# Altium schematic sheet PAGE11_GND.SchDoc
size 381 x 304 mm; SheetNumber: 12; SheetTotal: 28
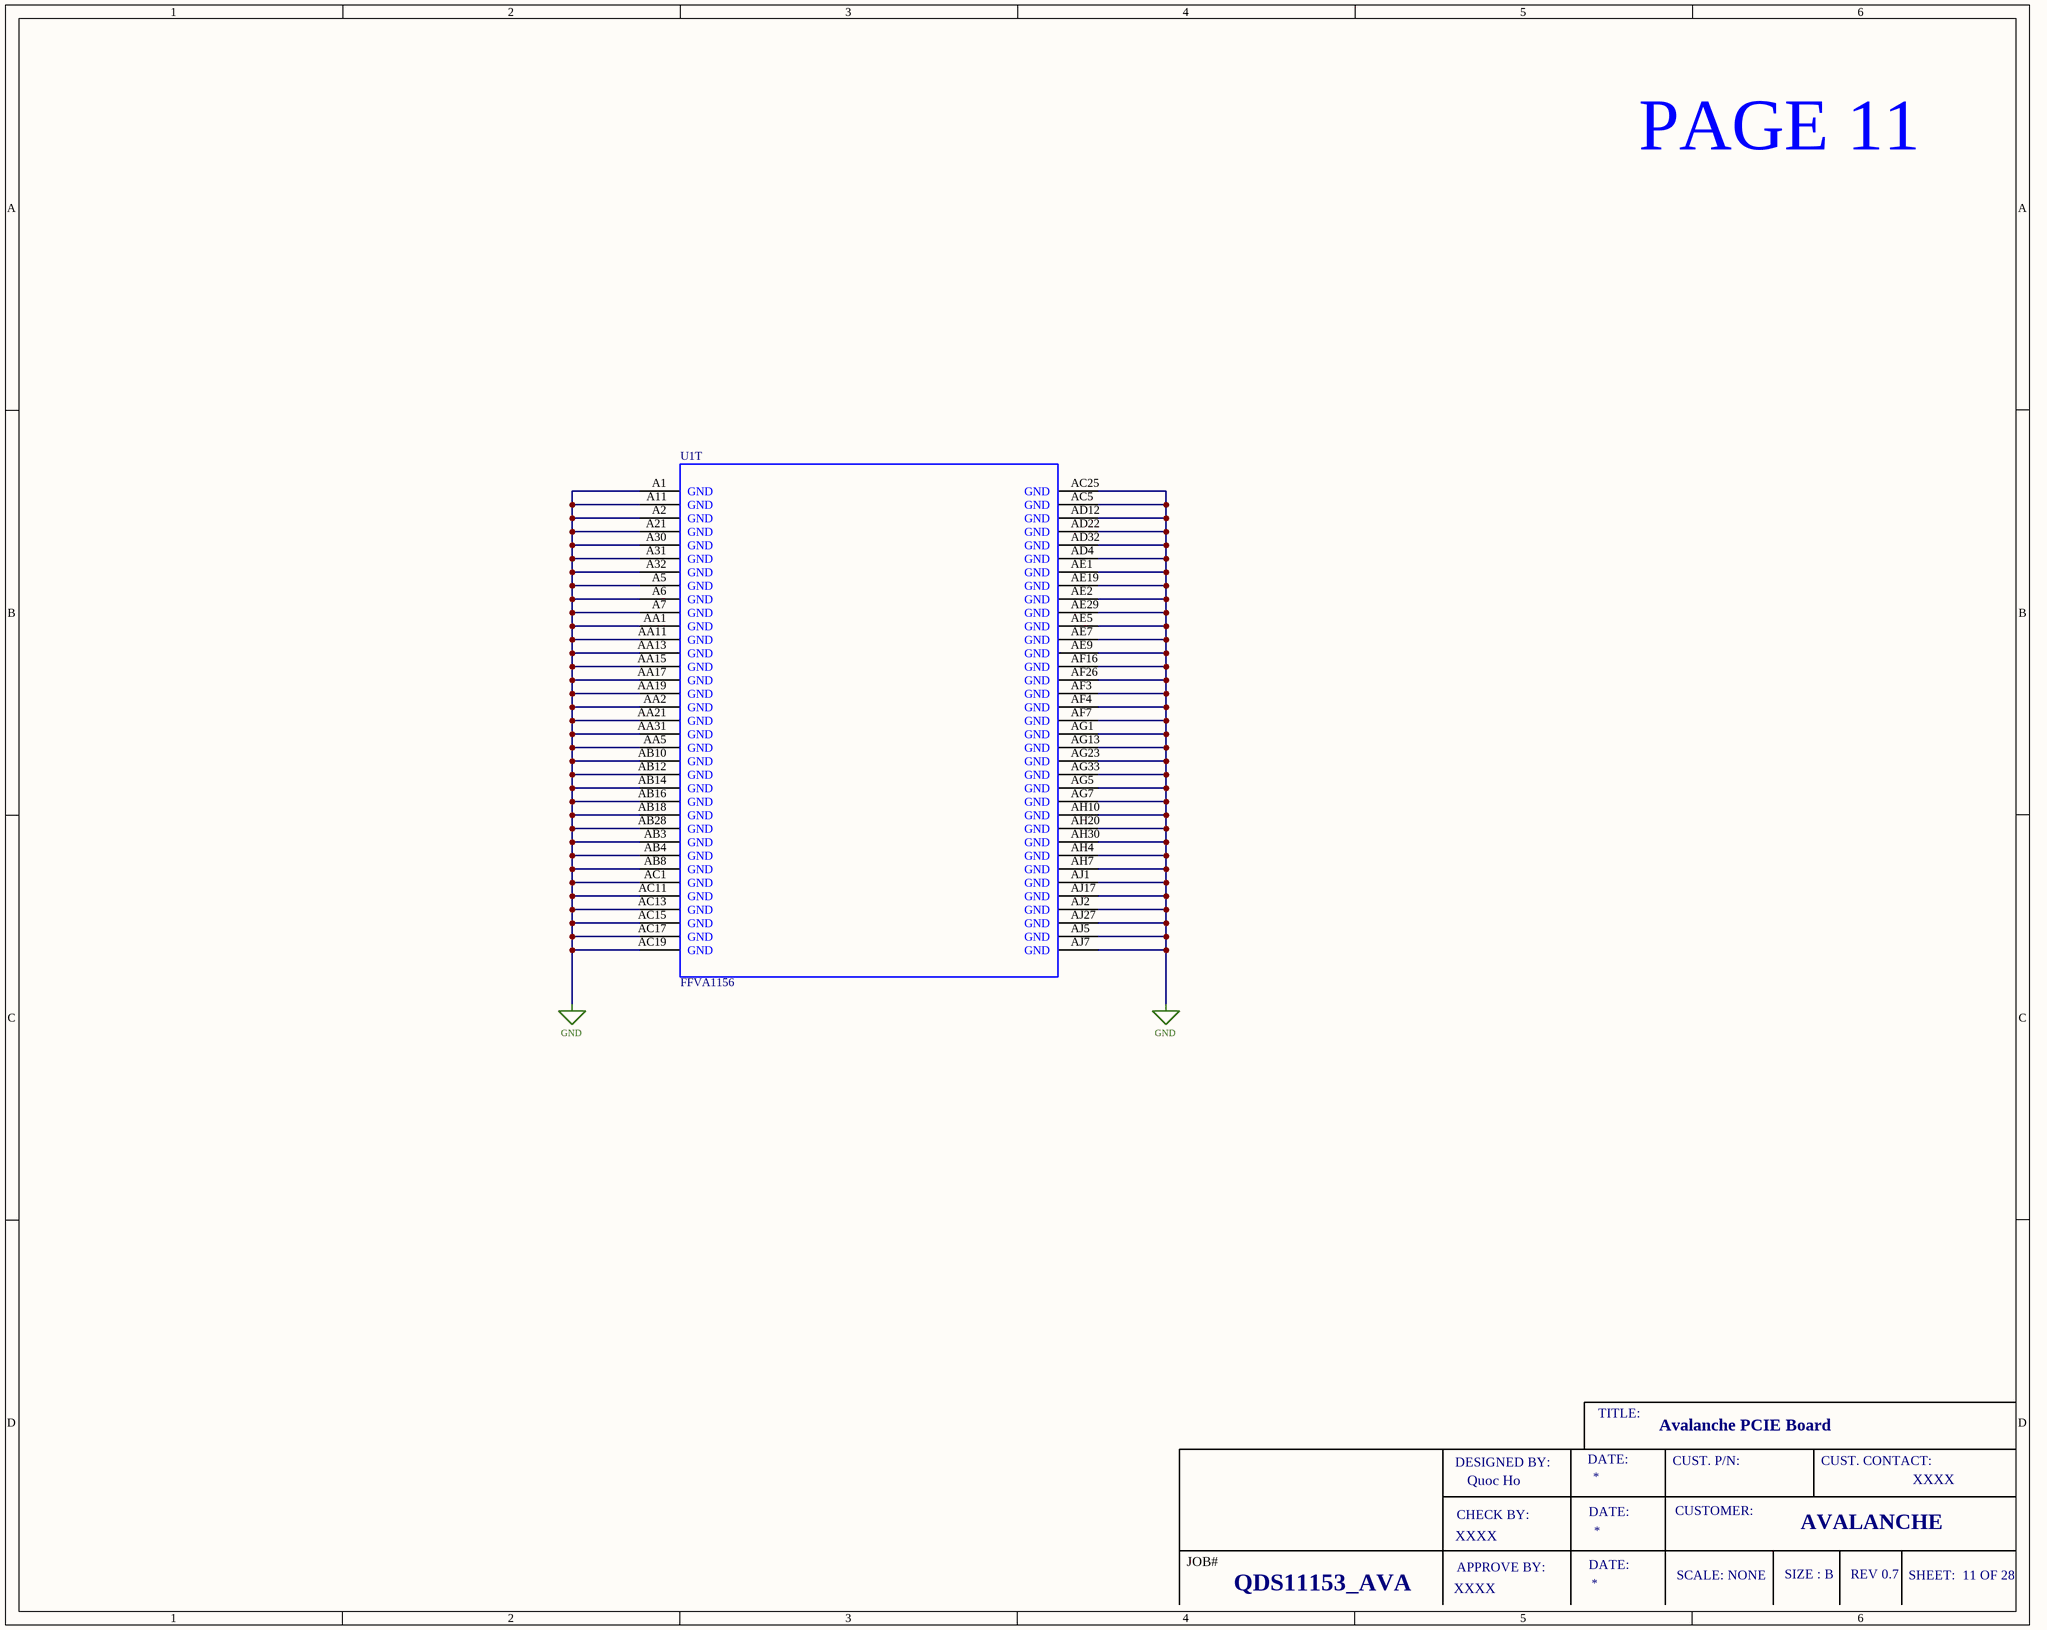
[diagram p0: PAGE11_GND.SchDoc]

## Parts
U1  FFVA1156  [FFVA1156]  (part T of 25)

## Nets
GND: U1.A1(GND) U1.A2(GND) U1.A5(GND) U1.A6(GND) U1.A7(GND) U1.A11(GND) U1.A21(GND) U1.A30(GND) U1.A31(GND) U1.A32(GND) U1.AA1(GND) U1.AA2(GND) U1.AA5(GND) U1.AA11(GND) U1.AA13(GND) U1.AA15(GND) U1.AA17(GND) U1.AA19(GND) U1.AA21(GND) U1.AA31(GND) U1.AB3(GND) U1.AB4(GND) U1.AB8(GND) U1.AB10(GND) U1.AB12(GND) U1.AB14(GND) U1.AB16(GND) U1.AB18(GND) U1.AB28(GND) U1.AC1(GND) U1.AC5(GND) U1.AC11(GND) U1.AC13(GND) U1.AC15(GND) U1.AC17(GND) U1.AC19(GND) U1.AC25(GND) U1.AD4(GND) U1.AD12(GND) U1.AD22(GND) U1.AD32(GND) U1.AE1(GND) U1.AE2(GND) U1.AE5(GND) U1.AE7(GND) U1.AE9(GND) U1.AE19(GND) U1.AE29(GND) U1.AF3(GND) U1.AF4(GND) U1.AF7(GND) U1.AF16(GND) U1.AF26(GND) U1.AG1(GND) U1.AG5(GND) U1.AG7(GND) U1.AG13(GND) U1.AG23(GND) U1.AG33(GND) U1.AH4(GND) U1.AH7(GND) U1.AH10(GND) U1.AH20(GND) U1.AH30(GND) U1.AJ1(GND) U1.AJ2(GND) U1.AJ5(GND) U1.AJ7(GND) U1.AJ17(GND) U1.AJ27(GND)

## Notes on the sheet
- PAGE 11
- TITLE:
- Avalanche PCIE Board
- DESIGNED BY:
- CHECK BY:
- Quoc Ho
- DATE:
- CUST. P/N:
- CUSTOMER:
- CUST. CONTACT:
- XXXX
- JOB#
- APPROVE BY:
- SCALE: NONE
- SIZE : B
- AVALANCHE
- REV 0.7
- SHEET:  11 OF 28
- QDS11153_AVA

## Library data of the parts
U1 = FFVA1156: IC FPGA 516 I/O 1156FCBGA; Manufacturer: AMD; Manufacturer Part Number: XCKU15P-1FFVA1156E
